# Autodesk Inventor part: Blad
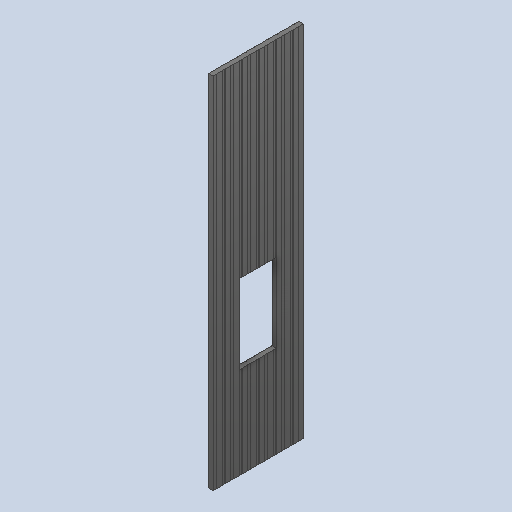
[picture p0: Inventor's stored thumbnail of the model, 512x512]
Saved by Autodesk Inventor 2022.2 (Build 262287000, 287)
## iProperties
Created: 2019-06
Part Number: Blad
Material: UHMW, Black
Document SubType Name: Modeling
Designer: cl
Density: 0.94 g/cm^3
Appearance: Smooth - Black
Author: cl
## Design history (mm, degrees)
sketch "Sketch4"
  geometry: L1 (0, 0)-(0, -35); L2 (0, -35)-(1.4, -36.4); L3 (1.4, -36.4)-(1.4, -96.4); L4 (1.4, -96.4)-(0, -97.8); L5 (0, 0)-(-23.6, 0); L6 (0, -97.8)-(-23.6, -97.8); L7 (-23.6, -97.8)-(-23.6, 0); L8 (-47.2, 0)-(-23.6, 0); L9 (-47.2, 0)-(-47.2, -35); L10 (-47.2, -35)-(-48.6, -36.4); L11 (-48.6, -36.4)-(-48.6, -96.4); L12 (-48.6, -96.4)-(-47.2, -97.8); L13 (-47.2, -97.8)-(-23.6, -97.8)
  constraints: 26 end point, 5 symmetric about line, 3 vertical, 2 horizontal
  dimensions: "d41" = 35 distance of L1.start L1.end; "d43" = 45 deg angle of L2 L1; "d44" = 60 distance of L2.end L3.end; "d45" = 45 deg angle of L3 L4; "d46" = 1.4 distance between parallel lines of L1 L3; "d47" = 1.4 horizontal distance of L3.end L4.end (derived); "d48" = 23.6 distance of L1.start L5.end
extrude "Extrusion2" new body sketch "Sketch4" distance "d49" = 3921 (derived); taper "d50" = 0 deg
sketch "Sketch5"
  geometry: L1 (-48.6, -96.4)-(-47.2, -97.8) reference; L2 (-47.2, -97.8)-(-47.2, -127.8); L3 (-47.2, -97.8)-(-17.2, -97.8); L4 (-47.2, -127.8)-(-48.6, -129.2); L5 (-48.6, -129.2)-(-48.6, -189.2); L6 (-47.2, -97.8)-(-23.6, -97.8); L7 (-47.2, -97.8)-(0, -97.8) reference; L8 (-23.6, -97.8)-(-23.6, -190.6); L9 (-48.6, -189.2)-(-47.2, -190.6); L10 (-47.2, -190.6)-(-23.6, -190.6); L11 (0, -97.8)-(-30, -97.8); L12 (0, -97.8)-(0, -127.8); L13 (0, -127.8)-(1.4, -129.2); L14 (1.4, -129.2)-(1.4, -189.2); L15 (0, -190.6)-(-23.6, -190.6); L16 (1.4, -189.2)-(0, -190.6); 1 further point
  constraints: 28 end point, 5 symmetric about line, 2 horizontal, 2 perpendicular, 2 vertical, 1 midpoint, 1 parallel
  dimensions: "d51" = 30 distance of L1.end L2.end; "d52" = 90 deg angle of L2 L3 (derived); "d54" = 1.4 distance between parallel lines of L2 L5; "d55" = 23.6 distance of L1.end L6.end; "d56" = 45 deg angle of L9 L5; "d57" = 1.4 distance from line of L5 L9.end; "d60" = 60 distance of L4.end L5.end
extrude "Extrusion3" join sketch "Sketch5" distance "d58" = 3921 (derived); taper "d59" = 0 deg
pattern_linear "Rectangular Pattern1" dims "d61" = 85.33405 (derived), "d63" = 92.8
sketch "Sketch7"
  geometry: L1 (-47.2, -855.9)-(0, -855.9); L2 (0, -855.9)-(0, -983.5); L3 (0, -983.5)-(-47.2, -983.5); L4 (-47.2, -983.5)-(-47.2, -855.9); L5 (0, 0)-(-47.2, 0) reference; L6 (-47.2, -97.8)-(-47.2, -127.8) reference; L7 (-47.2, -127.8)-(-48.6, -129.2) reference; L8 (-48.6, -129.2)-(-48.6, -189.2) reference; L9 (-48.6, -189.2)-(-47.2, -190.6) reference; L10 (-47.2, -190.6)-(-47.2, -220.6) reference; L11 (-47.2, -220.6)-(-48.6, -222) reference; L12 (-48.6, -222)-(-48.6, -282) reference; L13 (-48.6, -282)-(-47.2, -283.4) reference; L14 (-47.2, -283.4)-(-47.2, -313.4) reference; L15 (-47.2, -313.4)-(-48.6, -314.8) reference; L16 (-48.6, -314.8)-(-48.6, -374.8) reference; L17 (-48.6, -374.8)-(-47.2, -376.2) reference; L18 (0, -376.2)-(1.4, -374.8) reference; L19 (1.4, -374.8)-(1.4, -314.8) reference; L20 (1.4, -314.8)-(0, -313.4) reference; L21 (0, -313.4)-(0, -283.4) reference; L22 (0, -283.4)-(1.4, -282) reference; L23 (1.4, -282)-(1.4, -222) reference; L24 (1.4, -222)-(0, -220.6) reference; L25 (0, -220.6)-(0, -190.6) reference; L26 (0, -190.6)-(1.4, -189.2) reference; L27 (1.4, -189.2)-(1.4, -129.2) reference; L28 (1.4, -129.2)-(0, -127.8) reference; L29 (0, -127.8)-(0, -97.8) reference; L30 (-47.2, -35)-(-48.6, -36.4) reference; L31 (-48.6, -36.4)-(-48.6, -96.4) reference; L32 (-48.6, -96.4)-(-47.2, -97.8) reference; L33 (0, -97.8)-(1.4, -96.4) reference; L34 (1.4, -96.4)-(1.4, -36.4) reference; L35 (1.4, -36.4)-(0, -35) reference; L36 (0, -35)-(0, 0) reference; L37 (0, 0)-(-47.2, 0) reference; L38 (-47.2, 0)-(-47.2, -35) reference; L39 (-47.2, -376.2)-(-47.2, -406.2) reference; L40 (-47.2, -406.2)-(-48.6, -407.6) reference; L41 (-48.6, -407.6)-(-48.6, -467.6) reference; L42 (-48.6, -467.6)-(-47.2, -469) reference; L43 (-47.2, -469)-(-47.2, -499) reference; L44 (-47.2, -499)-(-48.6, -500.4) reference; L45 (-48.6, -500.4)-(-48.6, -560.4) reference; L46 (-48.6, -560.4)-(-47.2, -561.8) reference; L47 (0, -561.8)-(1.4, -560.4) reference; L48 (1.4, -560.4)-(1.4, -500.4) reference; L49 (1.4, -500.4)-(0, -499) reference; L50 (0, -499)-(0, -469) reference; L51 (0, -469)-(1.4, -467.6) reference; L52 (1.4, -467.6)-(1.4, -407.6) reference; L53 (1.4, -407.6)-(0, -406.2) reference; L54 (0, -406.2)-(0, -376.2) reference; L55 (-47.2, -561.8)-(-47.2, -591.8) reference; L56 (-47.2, -591.8)-(-48.6, -593.2) reference; L57 (-48.6, -593.2)-(-48.6, -653.2) reference; L58 (-48.6, -653.2)-(-47.2, -654.6) reference; L59 (0, -654.6)-(1.4, -653.2) reference; L60 (1.4, -653.2)-(1.4, -593.2) reference; L61 (1.4, -593.2)-(0, -591.8) reference; L62 (0, -591.8)-(0, -561.8) reference; L63 (-47.2, -654.6)-(-47.2, -684.6) reference; L64 (-47.2, -684.6)-(-48.6, -686) reference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
  constraints: 8 end point, 2 parallel, 1 horizontal, 1 perpendicular
  dimensions: "d67" = 983.5 distance between parallel lines of L5 L3 (derived)
extrude "Extrusion5" join sketch "Sketch7" distance "d68" = 3921 (derived); taper "d69" = 0 deg
sketch "Sketch10"
  geometry: L1 (195.35, 1862)-(595.35, 1862); L2 (595.35, 1862)-(595.35, 1000); L3 (595.35, 1000)-(195.35, 1000); L4 (195.35, 1000)-(195.35, 1862); L5 (395.35, 1000)-(395.35, 1862); L6 (195.35, 1000)-(595.35, 1000); L7 (595.35, 1000)-(595.35, 1862); L8 (595.35, 1862)-(195.35, 1862); L9 (195.35, 1862)-(195.35, 1000); L10 (395.35, 1862)-(395.35, 1000); 1 further point
  constraints: 20 end point, 4 midpoint, 4 parallel, 2 horizontal, 2 perpendicular, 1 collinear
  dimensions: "d82" = 862 distance of L1.end L2.end (derived); "d83" = 400 distance of L2.end L3.end (derived); "d86" = 491.75 distance from line of L5 point (-96.4, 0) (derived); "d92" = 1000 distance from line of point (-96.4, 0) L3 (derived); "d93" = 400 distance of L6.start L6.end (derived); "d94" = 862 distance of L6.end L7.end (derived); "d95" = 0.0001 distance between parallel lines of L3 L6 (derived)
extrude "Extrusion8" cut sketch "Sketch10" stored distance "d87" = 100; taper "d88" = 0 deg
body "Solid2"
node "Projected Loop1"
other parameters: "d24" = 45 deg, "BladBredd" = 987.5, "AntalVeck" = 9.88685 (computed from BladBredd) [user parameter], "Fönsterhöjd" = 862, "Blad2" = 1012.5, "Blad3" = 0, "Blad4" = 0, "Blad5" = 1012.5, "Blad6" = 2025, "MGJ12Djup" = 0, "MGJ12Bredd" = 0, "MGJ2Djup" = 0, "MGJ2Bredd" = 5012.5, "MGJ56Djup" = 0, "MGJ56Bredd" = 0, "MGJ23Djup" = 48, "MGJ45Djup" = 48, "GarageRegel5" = 0, "GarageRegel6" = 0, "Styrrulle2Djup" = 0, "FönsterhöjdStyrning" = 862, "FönsterKarm" = 54, "AndraGlasraden" = 0, "BrösthöjdStyrning2" = 0.0001
